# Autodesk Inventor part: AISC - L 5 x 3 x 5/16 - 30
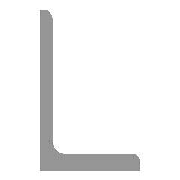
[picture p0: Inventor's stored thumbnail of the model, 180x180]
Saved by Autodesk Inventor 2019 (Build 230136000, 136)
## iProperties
Created: 2018-01
Part Number: AISC - L 5 x 3 x 5/16 - 30
Material: Steel, Mild
Description: Angle Steel
Document SubType Name: Modeling
Standard: ANSI
Designer: ElizabethC
Standards Organization: ANSI
Language: en-US
Size Designation: L 5 x 3 x 5/16
Categories: <MemberInstance><Categories><Category DisplayName="Structural Shapes" InternalName="089c4875-fa83-4c05-b084-43b9cc11f5ed" Mnemonic="GRDR"><CategoryParameter Dis
Stock Number: L 5 x 3 x 5/16
Mass: 8334.49 g
Surface Area: 2721.47 cm^2
Volume: 1061.72 cm^3
Density: 7.85 g/cm^3
Appearance: Semi-Polished
IsCustomPart: 1
_CCFamilyMember: 39
_CCFamilyDisplayName: ANSI L (Unequal angles) - Angle Steel — Sizes in parentheses have been withdrawn
_FrameMemberDoc: Frame Member File
_Version: 15.0.0
_GetPNFromCC: 1
Author: ElizabethC
G_L: 30.000 in
G_W: 3.000 in
G_H: 5.000 in
+1D6AAB70-836E-4B69-B8B5-54A6666A190B+CUTDETAIL1: Miter 45.00 deg
+E242FEE0-D0F7-4038-91EE-160DF7B02C19+CUTDETAIL2: Miter 45.00 deg
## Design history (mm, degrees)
node "Start plane"
node "End plane"
sketch "Sketch"
  geometry: L1 (70.612, 7.95)-(19.126, 7.95); L2 (0, 0)-(76.2, 0); L3 (76.2, 0)-(76.2, 2.362); L4 (-7.041, 0)-(21.538, 0); L5 (7.95, 19.126)-(7.95, 121.412); L6 (0, 127)-(0, 0); L7 (2.362, 127)-(0, 127); L8 (0, -8.041)-(0, 34.538); L9 (0, 155.397)-(0, -35.281) reference; L10 (-23.921, 0)-(94.237, 0) reference; A1 r 11.176 centre (19.126, 19.126) between (7.95, 19.126) and (19.126, 7.95); A2 r 5.588 centre (70.612, 2.362) between (76.2, 2.362) and (70.612, 7.95); A3 r 5.588 centre (2.362, 121.412) between (7.95, 121.412) and (2.362, 127); 3 further points
  constraints: 16 end point, 6 point on circle, 6 point on line, 6 tangent, 3 centre point, 2 collinear, 2 parallel, 1 equal radius
  dimensions: "d12" = 7.9502 distance between parallel lines of L5 L6 (= G_T); "d13" = 127 distance of L6.start L2.start (= G_H); "d14" = 76.2 distance of L2.start L2.end (= G_W); "d15" = 0 distance between parallel lines of L4 L2 (computed from ex); "d16" = 7.9502 distance between parallel lines of L2 L1 (= G_T); "d17" = 0 distance between parallel lines of L8 L6 (computed from ey); "d18" = 11.176 radius of A1 (= G_IR); "d19" = 5.588 radius of A2 (= G_ER)
extrude "Body" new body sketch "Sketch" stored distance "d4" = 762 (= G_L); taper "d5" = 0 deg
node "Driven Length"
  sketch "Sketch3"
    geometry: L1 (0, 0)-(10, 0) reference
    constraints: 2 end point, 1 horizontal
  workplane "Work Plane3"
  sketch "Sketch4"
    geometry: L1 (-2, 0)-(12, 0) reference; L2 (-2, 762)-(12, 762) reference
    dimensions: "d23" = 762 distance between parallel lines of L1 L2 (derived)
workplane "Work Plane4"
split "Split1"
workplane "Work Plane5"
split "Split2"
body "Solid1"
other parameters: "G_W" = 76.2 [user parameter; used in 1 equation term], "G_H" = 127 [user parameter; used in 1 equation term], "G_T" = 7.9502 [user parameter; used in 2 equation terms], "G_ER" = 5.588 [user parameter; used in 1 equation term], "G_IR" = 11.176 [user parameter; used in 1 equation term], "G_L" = 762 (= d23) [user parameter; used in 1 equation term], "ex" = 0 [user parameter; used in 1 equation term], "ey" = 0 [user parameter; used in 1 equation term], "G_OFFSET_START" = 0 [user parameter; used in 1 equation term], "G_OFFSET_END" = 0 [user parameter; used in 1 equation term], "d20" = 0 (computed from G_OFFSET_START), "d21" = 762 (= G_OFFSET_END + B_L), "B_L" = 762 [user parameter; used in 1 equation term], "d22" = 90 deg, "MAS" = 1.22029 [user parameter]
